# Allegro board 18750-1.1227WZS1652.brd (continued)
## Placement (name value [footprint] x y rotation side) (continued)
PC4521  SCD1U25V2KX-GP  [C402H22]  39.57 35.1 180 top
PC4522  SCD1U25V2KX-GP  [C402H22]  38.92 34.04 0 bottom
PC4523  SC10U25V5KX-GP  [C805H56]  46.48 32.08 180 bottom
PC4524  SC2D2U10V3KX-1GP  [C603H36]  42.57 39.82 0 bottom
PC4525  SC22U6D3V3MX-1-DL-GP  [C603H40]  56.29 130.58 180 top
PC4526  SC1KP50V2KX-1GP  [C402H22]  40.38 39.2 0 bottom
PC4527  SC22U6D3V3MX-1-DL-GP  [C603H40]  54.38 40.13 0 bottom
PC4529  SC22U6D3V3MX-1-DL-GP  [C603H40]  52.05 36.88 180 bottom
PC4530  SCD1U25V2KX-GP  [C402H22]  36.25 38.74 180 bottom
PC4531  SCD1U25V2KX-GP  [C402H22]  37.82 39.93 0 bottom
PC4532  SCD1U25V2KX-GP  [C402H22]  60.6 133.64 270 top
PC4533  SC1KP50V2KX-1GP  [C402H22]  62.89 132.26 90 top
PC4601  SC2200P50V2KX-2DLGP  [C402H22]  70.54 147.83 180 bottom
PC4602  SCD1U16V2KX-3DLGP  [C402H22]  84.89 151.49 90 top
PC4603  SCD1U25V2KX-1-DL-GP  [C402H22]  69.95 150.47 270 bottom
PC4604  SC330P50V2KX-3-DL-GP  [C402H22]  80.67 150.78 90 top
PC4605  SCD047U25V2KX-4-GP  [C402H22]  73.99 148.54 270 bottom
PC4606  SCD22U25V3KX-DL-GP  [C603H36]  74.91 152.4 270 top
PC4607  SC1U10V2KX-1DLGP  [C402H22]  77.6 152.25 0 top
PC4608  SCD022U16V2KX-3DLGP  [C402H22]  73.99 147.78 90 bottom
PC4610  SC33P50V2JN-3DLGP  [C402H22]  81.33 149.84 90 top
PC4611  SC2200P50V2KX-2DLGP  [C402H22]  73.99 150.83 270 bottom
PC4612  SC2200P50V2KX-2DLGP  [C402H22]  86.98 150.87 180 top
PC4613  SCD01U25V2KX-3DLGP  [C402H22]  77.35 151.13 90 top
PC4614  SC470P50V2KX-3DLGP  [C402H22]  86.95 147.98 90 top
PC4615  SCD01U50V2KX-1DLGP  [C402H22]  88.09 148.34 180 top
PC4616  SC1KP50V2KX-1DLGP  [C402H22]  74.08 149.4 270 top
PC4617  SC1KP50V2KX-1DLGP  [C402H22]  72.72 148.06 180 top
PC4618  SC470P50V2KX-3DLGP  [C402H22]  86.59 149.12 0 top
PC4619  SC1KP50V2KX-1DLGP  [C402H22]  88.73 150.32 0 bottom
PC4620  SCD01U50V2KX-1DLGP  [C402H22]  71.94 149.63 180 top
PC4621  SC680P50V2KX-2GP  [C402H22]  73.41 145.14 0 top
PC4622  SCD01U25V2KX-3DLGP  [C402H22]  81.43 148.18 270 top
PC4623  SC2200P50V2KX-2DLGP  [C402H22]  84.22 146.56 0 bottom
PC4624  SC33P50V2JN-3DLGP  [C402H22]  77.35 149.56 90 top
PC4625  SCD022U16V2KX-3DLGP  [C402H22]  87.99 145.96 180 top
PC4626  SCD022U16V2KX-3DLGP  [C402H22]  88.78 145.96 180 top
PC4628  SCD022U16V2KX-3DLGP  [C402H22]  85.8 149.25 270 bottom
PC4629  SC330P50V2KX-3-DL-GP  [C402H22]  77.35 148.77 270 top
PC4630  SCD047U25V2KX-4-GP  [C402H22]  84.52 146.74 90 top
PC4631  SCD1U25V2KX-1-DL-GP  [C402H22]  73.49 145.1 0 bottom
PC4632  SC2200P50V2KX-2DLGP  [C402H22]  75.24 145.72 90 top
PC4633  SCD1U25V2KX-1-DL-GP  [C402H22]  87.2 146.83 180 top
PC4634  SCD047U25V2KX-4-GP  [C402H22]  75.36 145.47 270 bottom
PC4635  SCD01U25V2KX-3DLGP  [C402H22]  69.97 146.99 90 top
PC4637  SCD01U25V2KX-3DLGP  [C402H22]  78.71 146.86 180 top
PC4638  SC330P50V2KX-3-DL-GP  [C402H22]  80.58 146.87 180 top
PC4639  SC33P50V2JN-3DLGP  [C402H22]  79.48 146.86 180 top
PC4640  SC2200P50V2KX-2DLGP  [C402H22]  78.82 144.29 180 top
PC4641  SC330P50V2KX-3-DL-GP  [C402H22]  77.2 144.25 180 top
PC4642  SC1KP50V2KX-1DLGP  [C402H22]  69.88 146.71 270 bottom
PC4643  SC1KP50V2KX-1DLGP  [C402H22]  71.81 144.7 0 bottom
PC4644  SCD01U50V2KX-1DLGP  [C402H22]  78.01 144.25 180 top
PC4651  SC1KP50V2KX-1DLGP  [C402H22]  86.21 150.88 180 top
PC4652  SCD022U16V2KX-3DLGP  [C402H22]  69.96 147.8 90 top
PC4653  SCD047U25V2KX-4-GP  [C402H22]  85.8 148.48 270 bottom
PC4654  SCD022U16V2KX-3DLGP  [C402H22]  85.79 147.71 270 bottom
PC4701  SC10U25V3MX-GP  [C603H40]  69.32 135.61 0 top
PC4702  SC10U25V3MX-GP  [C603H40]  71.78 136.17 90 top
PC4703  SC10U25V3MX-GP  [C603H40]  71.83 138.53 90 top
PC4704  SC10U25V3MX-GP  [C603H40]  71.71 140.03 90 top
PC4706  SC1KP50V2KX-1DLGP  [C402H22]  68.61 132.26 180 top
PC4707  SCD22U25V3KX-DL-GP  [C603H36]  67.67 136.81 180 top
PC4708  SC1U10V2KX-1DLGP  [C402H22]  66.58 139.88 0 bottom
PC4766  SC1U10V2KX-1DLGP  [C402H22]  64.27 135.48 0 top
PC4802  SC10U25V3MX-GP  [C603H40]  86.11 142.17 90 bottom
PC4803  SC10U25V3MX-GP  [C603H40]  86.13 140.69 90 bottom
PC4804  SC10U25V3MX-GP  [C603H40]  86.19 139.24 90 bottom
PC4805  SC10U25V3MX-GP  [C603H40]  87.1 135.61 180 bottom
PC4808  SCD22U25V3KX-DL-GP  [C603H36]  83.54 140.62 180 bottom
PC4809  SC1U10V2KX-1DLGP  [C402H22]  79.35 138.3 180 top
PC4810  SC1KP50V2KX-1DLGP  [C402H22]  85.52 132.26 180 top
PC4811  SCD22U25V3KX-DL-GP  [C603H36]  78.21 136.68 180 top
PC4812  SC1U10V2KX-1DLGP  [C402H22]  75.54 136.32 0 top
PC4813  SC1KP50V2KX-1DLGP  [C402H22]  74.93 132.26 180 top
PC4814  SC10U25V3MX-GP  [C603H40]  78.25 141.38 270 top
PC4815  SC10U25V3MX-GP  [C603H40]  78.25 139.98 90 bottom
PC4816  SC10U25V3MX-GP  [C603H40]  78.25 141.71 90 bottom
PC4817  SC10U25V3MX-GP  [C603H40]  78.46 139.93 270 top
PC4866  SC1U10V2KX-1DLGP  [C402H22]  74.78 136.32 0 top
PC4877  SC1U10V2KX-1DLGP  [C402H22]  80.11 135.61 270 top
PC5001  SC2D2U10V3KX-1DLGP-U  [C603H36]  98.76 139.8 90 bottom
PC5002  SC10U25V5KX-DL-GP  [C805H58]  91.54 138.76 90 bottom
PC5003  SC10U25V5KX-DL-GP  [C805H58]  91.54 140.49 90 bottom
PC5004  SCD1U25V2KX-1-DL-GP  [C402H22]  95.79 138.28 270 bottom
PC5005  SCD22U25V3KX-DL-GP  [C603H36]  97.89 138.43 0 top
PC5102  SCD1U25V2KX-1-DL-GP  [C402H22]  119.74 30.89 270 bottom
PC5103  SC1U10V2KX-L1-GP  [C402H22]  112.04 30.31 180 top
PC5104  SC22U6D3V3MX-L1-GP  [C603H40]  120.88 38.99 270 bottom
PC5105  SC22U6D3V3MX-L1-GP  [C603H40]  111.33 40.23 90 bottom
PC5106  SC22U6D3V3MX-L1-GP  [C603H40]  111.33 39.04 90 bottom
PC5107  SC22U6D3V3MX-L1-GP  [C603H40]  120.88 40.16 270 bottom
PC5111  SC68P50V2JN-1DLGP  [C402H22]  91.39 37.06 90 top
PC5112  SC10U6D3V3MX-DL-GP  [C603H36]  92.5 40.23 0 bottom
PC5113  SC10U6D3V3MX-DL-GP  [C603H36]  93.69 40.22 0 bottom
PC5114  SC1U6D3V1MX-GP  [C0201H14]  117.45 30.13 270 top
PC5115  SC10U25V5KX-L-GP  [C805H56]  120.5 35.71 0 bottom
PC5116  SC10U6D3V3MX-L-GP  [C603H38]  119.18 29.31 180 bottom
PC5117  SC10U6D3V3MX-L-GP  [C603H38]  120.35 29.31 180 bottom
PC5118  SC1500P50V2KX-2GP  [C402H22]  112.25 35.15 0 top
PC5119  SC10U25V5KX-L-GP  [C805H56]  122.23 36.48 0 bottom
PC5120  SC1U10V2KX-1DLGP  [C402H22]  97.64 37.21 270 top
PC5121  SC4D7U6D3V2MX-1-GP  [C402H22]  111.15 30.38 180 top
PC5122  SCD1U25V2KX-1-DL-GP  [C402H22]  115.04 32.89 270 top
PC5123  SCD1U25V2KX-1-DL-GP  [C402H22]  117.5 28.6 270 top
PC5124  SC10U6D3V3MX-DL-GP  [C603H36]  99.89 36.65 270 bottom
PC5127  SCD1U25V2KX-1-DL-GP  [C402H22]  97.67 35.61 270 top
PC5201  SC22U6D3V3MX-1-DL-GP  [C603H40]  105.91 128.92 90 top
PC5202  SC4D7U25V5KX-DL-GP  [C805H54]  98.05 138.33 90 bottom
PC5203  SC22U6D3V3MX-1-DL-GP  [C603H40]  105.91 130.09 90 top
PC5204  SCD1U25V2KX-1-DL-GP  [C402H22]  102.15 135.71 0 top
PC5205  SC22U6D3V3MX-1-DL-GP  [C603H40]  105.91 128.92 270 bottom
PC5206  SC22U6D3V3MX-1-DL-GP  [C603H40]  105.91 130.09 270 bottom
PC5208  SCD1U25V2KX-1-DL-GP  [C402H22]  105.46 127.95 270 bottom
PC5209  SC10U25V5KX-DL-GP  [C805H58]  105.9 138.79 0 bottom
PC5210  SC10U25V5KX-DL-GP  [C805H58]  106.48 134.43 180 bottom
PC5211  SC10U25V5KX-DL-GP  [C805H58]  107.62 138.79 0 bottom
PC5212  SC220P50V2KX-3DLGP  [C402H22]  102.8 141.15 270 bottom
PC5213  SCD01U25V2KX-3DLGP  [C402H22]  100.84 137.19 90 top
PC5214  SCD1U25V2KX-1-DL-GP  [C402H22]  105.24 134.57 180 bottom
PC5215  SC1KP50V2KX-1DLGP  [C402H22]  100.16 141.33 0 bottom
PC5216  SC10U25V5KX-DL-GP  [C805H58]  109.88 140.23 270 bottom
PC5217  SC22U6D3V3MX-1-DL-GP  [C603H40]  98.17 125.05 90 bottom
PC5301  SC22U6D3V3MX-L1-GP  [C603H40]  72.24 36.7 90 bottom
PC5302  SC22U6D3V3MX-L1-GP  [C603H40]  64.82 40.64 90 bottom
PC5303  SC22U6D3V3MX-L1-GP  [C603H40]  67.21 40.64 270 bottom
PC5305  SC22P50V2JN-L-GP  [C402H22]  69.01 40.62 180 bottom
PC5307  SC1U6D3V1MX-GP  [C0201H14]  68.56 40.9 270 top
PC8501  SC10U25V3MX-3-GP  [C603H40]  140.31 81.74 0 top
PC8502  SC10U25V3MX-3-GP  [C603H40]  139.14 81.74 0 top
PC8503  SCD1U25V2KX-1-DL-GP  [C402H22]  141.66 82.73 90 top
PC8504  SC10U25V3MX-3-GP  [C603H40]  157.13 82.17 0 top
PC8505  SC10U25V3MX-3-GP  [C603H40]  154.16 82.83 270 top
PC8506  SCD1U25V2KX-1-DL-GP  [C402H22]  154.97 81.51 0 top
PC8507  SC330P50V2JN-1-DL-GP  [C402H22]  147.41 90.27 0 top
PC8508  SC330P50V2JN-1-DL-GP  [C402H22]  146.57 90.27 0 top
PC8550  SC1U10V2KX-1DLGP  [C402H22]  145.06 81.36 270 top
PC8551  SCD1U25V2KX-1-DL-GP  [C402H22]  143.42 76.4 90 top
PC8552  SC1KP50V2KX-1DLGP  [C402H22]  148.57 78.41 90 bottom
PC8553  SCD1U25V2KX-1-DL-GP  [C402H22]  141.02 78.77 180 bottom
PC8554  SCD01U50V2KX-1DLGP  [C402H22]  140.47 77.04 270 top
PC8555  SC2700P50V2KX-1-DL-GP  [C402H22]  141.46 75.21 225 top
PC8556  SCD1U25V2KX-1-DL-GP  [C402H22]  146.34 78.4 270 top
PC8558  SC47P50V2JN-5DLGP  [C402H22]  139.2 77.98 0 top
PC8559  SC47P50V2JN-5DLGP  [C402H22]  140.06 79.45 180 top
PC8560  SC47P50V2JN-5DLGP  [C402H22]  144.86 78.39 90 top
PC8561  SC10U25V3MX-3-GP  [C603H40]  140.31 81.74 180 bottom
PC8562  SC10U25V3MX-3-GP  [C603H40]  139.14 81.74 180 bottom
PC8572  SCD1U25V2KX-1-DL-GP  [C402H22]  149.91 81.9 0 bottom
PC8573  SC33P50V2JN-3DLGP  [C402H22]  143.93 81.05 180 top
PC8575  SCD1U25V2KX-1-DL-GP  [C402H22]  143.51 82.22 270 bottom
PC8576  SC10U25V3MX-3-GP  [C603H40]  155.93 81.54 0 top
PC8578  SC10U25V3MX-3-GP  [C603H40]  154.18 82.86 90 bottom
PC8602  SC330P50V2KX-3GP  [C402H22]  111 153.7 180 bottom
PC8609  SCD01U25V2KX-3DLGP  [C402H22]  111.75 145.82 180 bottom
PC8610  SC10U25V5KX-GP  [C805H56]  110.47 145.9 180 bottom
PC8611  SC22U6D3V3MX-1-DL-GP  [C603H40]  118.95 150.7 0 bottom
PC8613  SC22U6D3V3MX-1-DL-GP  [C603H40]  120.12 150.7 0 bottom
PC8614  SCD1U16V2KX-3GP  [C402H22]  120.83 144.97 270 bottom
PC8615  SC10U25V5KX-GP  [C805H56]  108.74 145.9 180 bottom
PC8617  SC2D2U10V3KX-1GP  [C603H36]  113.39 151.06 270 bottom
PC8618  SC1U6D3V1MX-GP  [C0201H14]  111.71 152.66 270 bottom
PC8619  SCD1U25V2KX-GP  [C402H22]  113.41 148.85 0 bottom
PC8620  SC22U6D3V3MX-1-DL-GP  [C603H40]  118.95 150.7 180 top
PC8621  SC22U6D3V3MX-1-DL-GP  [C603H40]  117.78 150.7 0 bottom
PC8627  SC10U6D3V3MX-GP  [C603H38]  107.09 143.1 0 bottom
PC8628  SC22U6D3V3MX-1-GP  [C603H40]  117.27 140.51 180 bottom
PC8629  SC1U6D3V1MX-GP  [C0201H14]  109.1 143.26 0 bottom
PC8630  SC10U6D3V3MX-GP  [C603H38]  108.26 143.33 0 bottom
PC8631  SC22U6D3V3MX-1-GP  [C603H40]  116.06 140.51 180 bottom
PC8632  SC22P50V2JN-4GP  [C402H22]  110.82 141.45 270 top
PC8633  SC1U6D3V1MX-GP  [C0201H14]  111.71 152.15 270 bottom
PC8634  SC1U6D3V1MX-GP  [C0201H14]  109.6 143.26 0 bottom
PD4401  BAT54C-12-GP  [SOT-23-9H44]  198.43 42.19 180 bottom
PD4404  L1SS355T1G-GP  [SOD323AKH44]  214.3 45.47 270 bottom
PD4407  RB520S30-GP  [SOD523AKH26]  192.03 39.68 90 bottom
PD4408  BAT54C-12-GP  [SOT-23-9H44]  194.95 40.95 180 bottom
PD4409  RB520S30-GP  [SOD523AKH26]  191.7 41.53 0 bottom
PD5101  AZ4024-01L-R7G-GP  [SOD323AKH40]  117.17 31.45 90 top
PG4401  GAP-CLOSE-PWR-3-GP  [GAP-CLOSE-PWR-3]  183.87 56.31 0 bottom
PG4402  GAP-CLOSE-PWR-3-GP  [GAP-CLOSE-PWR-3]  185.4 56.31 180 bottom
PG4405  GAP-CLOSE-PWR-3-GP  [GAP-CLOSE-PWR-3]  173.49 40.64 90 bottom
PG4406  GAP-CLOSE-PWR-3-GP  [GAP-CLOSE-PWR-3]  171.96 40.64 90 bottom
PG4408  GAP-CLOSE-PWR-3-GP  [GAP-CLOSE-PWR-3]  209.29 41.59 90 top
PG4415  GAP-CLOSE-PWR-0805-NP-5-GP  [GAP-CLOSE-PWR-0805-NP-5]  183.09 38.28 270 bottom
PG4419  GAP-CLOSE-PWR-0805-NP-5-GP  [GAP-CLOSE-PWR-0805-NP-5]  185.04 59.23 90 bottom
PG4422  GAP-CLOSE-PWR-0805-NP-5-GP  [GAP-CLOSE-PWR-0805-NP-5]  172.06 33.48 180 bottom
PG4423  GAP-CLOSE-PWR-0805-NP-5-GP  [GAP-CLOSE-PWR-0805-NP-5]  176.15 39.93 180 bottom
PG4527  GAP-CLOSE-PWR-3-GP  [GAP-CLOSE-PWR-3]  42.45 39.35 90 top
PG4528  GAP-CLOSE-PWR-3-GP  [GAP-CLOSE-PWR-3]  44.28 37.77 0 top
PG4530  GAP-CLOSE-PWR-3-GP  [GAP-CLOSE-PWR-3]  62.07 130.99 270 top
PG4532  GAP-CLOSE-PWR-3-GP  [GAP-CLOSE-PWR-3]  62.34 132.33 90 bottom
PG4707  GAP-CLOSE-PWR-3-GP  [GAP-CLOSE-PWR-3]  67.34 129.11 90 bottom
PG4708  GAP-CLOSE-PWR-3-GP  [GAP-CLOSE-PWR-3]  67.34 126.95 270 bottom
PG4808  GAP-CLOSE-PWR-3-GP  [GAP-CLOSE-PWR-3]  84.46 129.06 90 bottom
PG4809  GAP-CLOSE-PWR-3-GP  [GAP-CLOSE-PWR-3]  84.46 126.9 270 bottom
PG4813  GAP-CLOSE-PWR-3-GP  [GAP-CLOSE-PWR-3]  76.84 129.08 90 bottom
PG4815  GAP-CLOSE-PWR-3-GP  [GAP-CLOSE-PWR-3]  76.84 126.85 270 bottom
PG5001  GAP-CLOSE-PWR-3-GP  [GAP-CLOSE-PWR-3]  92.94 128.78 270 bottom
PG5002  GAP-CLOSE-PWR-3-GP  [GAP-CLOSE-PWR-3]  94.36 139.96 0 bottom
PG5003  GAP-CLOSE-PWR-3-GP  [GAP-CLOSE-PWR-3]  94.36 139.19 0 bottom
PG5011  GAP-CLOSE-PWR-3-GP  [GAP-CLOSE-PWR-3]  92.94 130.94 90 bottom
PG5101  GAP-CLOSE-PWR-3-GP  [GAP-CLOSE-PWR-3]  120.12 34.11 270 top
PG5102  GAP-CLOSE-PWR-3-GP  [GAP-CLOSE-PWR-3]  120.88 34.11 270 top
PG5103  GAP-CLOSE-PWR-3-GP  [GAP-CLOSE-PWR-3]  115.52 42.33 90 top
PG5104  GAP-CLOSE-PWR-3-GP  [GAP-CLOSE-PWR-3]  121.64 34.11 270 top
PG5105  GAP-CLOSE-PWR-3-GP  [GAP-CLOSE-PWR-3]  114.75 42.33 90 top
PG5106  GAP-CLOSE-PWR-3-GP  [GAP-CLOSE-PWR-3]  116.28 42.33 90 top
PG5107  GAP-CLOSE-PWR-3-GP  [GAP-CLOSE-PWR-3]  118.56 42.33 90 top
PG5108  GAP-CLOSE-PWR-3-GP  [GAP-CLOSE-PWR-3]  117.8 42.33 90 top
PG5109  GAP-CLOSE-PWR-3-GP  [GAP-CLOSE-PWR-3]  117.04 42.33 90 top
PG5110  GAP-CLOSE-PWR-3-GP  [GAP-CLOSE-PWR-3]  121.21 42.32 270 top
PG5111  GAP-CLOSE-PWR-3-GP  [GAP-CLOSE-PWR-3]  119.97 41.3 180 top
PG5112  GAP-CLOSE-PWR-3-GP  [GAP-CLOSE-PWR-3]  94.9 39.6 180 top
PG5113  GAP-CLOSE-PWR-3-GP  [GAP-CLOSE-PWR-3]  94.9 40.36 180 top
PG5114  GAP-CLOSE-PWR-3-GP  [GAP-CLOSE-PWR-3]  82.26 36.51 270 top
PG5116  GAP-CLOSE-PWR-3-GP  [GAP-CLOSE-PWR-3]  121.97 42.32 270 top
PG5122  GAP-CLOSE-PWR-3-GP  [GAP-CLOSE-PWR-3]  99.19 35.92 180 top
PG5201  GAP-CLOSE-PWR-3-GP  [GAP-CLOSE-PWR-3]  99.85 126.26 270 top
PG5202  GAP-CLOSE-PWR-3-GP  [GAP-CLOSE-PWR-3]  99.09 126.26 270 top
PG5203  GAP-CLOSE-PWR-3-GP  [GAP-CLOSE-PWR-3]  102.14 126.26 270 top
PG5204  GAP-CLOSE-PWR-3-GP  [GAP-CLOSE-PWR-3]  103.66 126.26 270 top
PG5205  GAP-CLOSE-PWR-3-GP  [GAP-CLOSE-PWR-3]  104.42 126.26 270 top
PG5206  GAP-CLOSE-PWR-3-GP  [GAP-CLOSE-PWR-3]  101.37 126.26 270 top
PG5207  GAP-CLOSE-PWR-3-GP  [GAP-CLOSE-PWR-3]  102.9 126.26 270 top
PG5208  GAP-CLOSE-PWR-3-GP  [GAP-CLOSE-PWR-3]  105.18 126.26 270 top
PG5209  GAP-CLOSE-PWR-3-GP  [GAP-CLOSE-PWR-3]  105.95 126.26 270 top
PG5210  GAP-CLOSE-PWR-3-GP  [GAP-CLOSE-PWR-3]  106.1 137.64 270 top
PG5211  GAP-CLOSE-PWR-3-GP  [GAP-CLOSE-PWR-3]  100.61 126.26 270 top
PG5212  GAP-CLOSE-PWR-3-GP  [GAP-CLOSE-PWR-3]  106.86 137.64 270 top
PG5214  GAP-CLOSE-PWR-3-GP  [GAP-CLOSE-PWR-3]  107.62 137.64 270 top
PG5223  GAP-CLOSE-PWR-6-GP  [GAP-CLOSE-PWR]  105.62 126.24 180 bottom
PG5301  GAP-CLOSE-PWR-3-GP  [GAP-CLOSE-PWR-3]  74.18 37.46 180 bottom
PG5302  GAP-CLOSE-PWR-3-GP  [GAP-CLOSE-PWR-3]  74.18 36.69 180 bottom
PG5303  GAP-CLOSE-PWR-3-GP  [GAP-CLOSE-PWR-3]  60.76 41.91 180 top
PG5304  GAP-CLOSE-PWR-3-GP  [GAP-CLOSE-PWR-3]  60.76 40.39 180 top
PG5305  GAP-CLOSE-PWR-3-GP  [GAP-CLOSE-PWR-3]  60.76 41.15 180 top
PG8605  GAP-CLOSE-PWR-3-GP  [GAP-CLOSE-PWR-3]  106.94 141.15 90 bottom
PG8608  GAP-CLOSE-PWR-3-GP  [GAP-CLOSE-PWR-3]  118.11 143.82 0 top
PG8609  GAP-CLOSE-PWR-3-GP  [GAP-CLOSE-PWR-3]  120.84 148.11 0 top
PG8610  GAP-CLOSE-PWR-3-GP  [GAP-CLOSE-PWR-3]  120.84 147.35 0 top
PG8611  GAP-CLOSE-PWR-3-GP  [GAP-CLOSE-PWR-3]  120.84 146.59 0 top
PG8612  GAP-CLOSE-PWR-3-GP  [GAP-CLOSE-PWR-3]  120.84 145.83 0 top
PG8613  GAP-CLOSE-PWR-3-GP  [GAP-CLOSE-PWR-3]  116.28 150.23 90 top
PG8614  GAP-CLOSE-PWR-3-GP  [GAP-CLOSE-PWR-3]  110.62 146.23 90 top
PG8615  GAP-CLOSE-PWR-3-GP  [GAP-CLOSE-PWR-3]  108.33 146.23 90 top
PG8616  GAP-CLOSE-PWR-3-GP  [GAP-CLOSE-PWR-3]  109.1 146.23 90 top
PG8617  GAP-CLOSE-PWR-3-GP  [GAP-CLOSE-PWR-3]  109.86 146.23 90 top
PG8618  GAP-CLOSE-PWR-3-GP  [GAP-CLOSE-PWR-3]  120.84 146.6 0 bottom
PG8619  GAP-CLOSE-PWR-3-GP  [GAP-CLOSE-PWR-3]  120.84 147.36 0 bottom
PG8620  GAP-CLOSE-PWR-3-GP  [GAP-CLOSE-PWR-3]  120.84 148.12 0 bottom
PG8621  GAP-CLOSE-PWR-3-GP  [GAP-CLOSE-PWR-3]  120.84 145.83 0 bottom
PG8622  GAP-CLOSE-PWR-3-GP  [GAP-CLOSE-PWR-3]  118.11 143.05 0 top
PL4401  COIL-2D2UH-11-GP  [L11510030H158]  184.97 49.79 90 bottom
PL4402  COIL-4D7UH-33-GP  [L7066-1830-UH119]  184.97 49.79 90 bottom
PL4501  IND-1D5UH-23-GP-U  [L7066-1830-UH119]  57.74 126.8 90 bottom
PL4502  IND-1D5UH-23-GP-U  [L7066-1830-UH119]  47.35 37.69 270 bottom
PL4701  IND-D15UH-33-GP  [L7366-1830H119]  67.41 127.99 180 bottom
PL4702  HCB2012KF-800T50-GP-U  [L20125H42]  71.78 142.98 90 bottom
PL4703  HCB2012KF-800T50-GP-U  [L20125H42]  71.78 141.25 90 bottom
PL4801  IND-D15UH-33-GP  [L7366-1830H119]  84.03 127.99 180 bottom
PL4802  IND-D15UH-33-GP  [L7366-1830H119]  76.79 127.99 180 bottom
PL4803  HCB2012KF-800T50-GP-U  [L20125H42]  94.39 143.05 90 bottom
PL4804  HCB2012KF-800T50-GP-U  [L20125H42]  94.39 141.33 90 bottom
PL5001  IND-D47UH-22-GP-U  [L7066-1830-UH119]  92.94 129.8 180 bottom
PL5101  COIL-1UH-34-GP-U1  [L7066-1830-UH119]  116.08 36.73 0 bottom
PL5201  COIL-1UH-34-GP-U1  [L7066-1830-UH119]  101.14 129.77 180 bottom
PL5301  IND-1UH-300-GP  [L2520-D620H48]  66.55 37.92 0 bottom
PL8508  COIL-D15UH-2-GP  [L7366-1930H158]  150.82 93.41 0 bottom
PL8509  COIL-D15UH-2-GP  [L7366-1930H158]  143.66 93.41 0 bottom
PL8602  IND-1UH-300-GP  [L2520-D620H48]  114.81 142.98 270 bottom
PL8603  COIL-1UH-73-GP  [L4947-1115H119]  116.98 146.85 270 bottom
PQ4402  2N7002K-2-GP  [SOT23DGS2D4H44]  159.85 94.49 180 bottom
PQ4405  2N7002KDW-1-GP  [SOT-363H44]  205.12 44.32 270 bottom
PQ4408  MMBT3906-5-GP-U  [SOT23CBE2D4H46-U]  210.7 44.65 180 bottom
PQ4415  2N7002KDW-1-GP  [SOT-363H44]  207.93 42.04 180 bottom
PQ4416  2N7002KDW-1-GP  [SOT-363H44]  207.52 46.2 0 bottom
PQ4417  2N7002K-2-GP  [SOT23DGS2D4H44]  11.23 128.78 180 top
PQ4418  2N7002KDW-1-GP  [SOT-363H44]  11.76 125.76 180 top
PR4401  D02R6F-GP  [R1206H24]  184.64 56.32 270 bottom
PR4402  2D2R3-1-U-GP  [R603H22]  200.66 54.13 180 bottom
PR4403  2D2R5J-1-GP  [R805H24]  207.57 52.68 270 bottom
PR4404  402KR2F-GP  [R402H16]  207.19 52.76 0 top
PR4405  4D7R2F-GP  [R402H16]  198.41 53.17 90 bottom
PR4406  100KR2F-L1-GP  [R402H16]  203.66 51.08 0 top
PR4407  D01R3721F-GP-U  [R3720H40]  172.77 38.46 90 bottom
PR4409  100KR2F-L1-GP  [R402H16]  205.62 44.96 0 top
PR4410  105KR2F-1-GP  [R402H16]  202.88 47.51 90 top
PR4411  499R2F-2-GP  [R402H16]  196.04 45.01 270 top
PR4412  -  [0R0402-PAD]  202.59 44.65 0 bottom
PR4413  7K32R2F-GP  [R402H16]  201.22 47.64 90 top
PR4414  -  [0R0805-PAD]  193.14 52.45 0 top
PR4416  2D2R3J-2-GP  [R603H22]  194.88 50.38 0 top
PR4417  100KR2F-L1-GP  [R402H16]  205.29 48.8 90 top
PR4420  0R3J-0-U-GP  [R603H22]  186.36 44.25 270 top
PR4422  1R2F-GP  [R402H16]  193.16 54.97 90 top
PR4423  1R2F-GP  [R402H16]  193.16 55.76 90 top
PR4424  1R2F-GP  [R402H16]  184.89 42.04 90 top
PR4425  1R2F-GP  [R402H16]  184.89 42.83 90 top
PR4426  196KR2F-GP  [R402H16]  207.5 47.79 90 top
PR4427  100KR2F-L2-GP  [R402H16]  207.64 41.67 0 top
PR4429  100KR2F-L2-GP  [R402H16]  208.43 41.67 0 top
PR4430  -  [0R0402-PAD]  13.67 129.74 180 top
PR4431  100KR2J-1-GP  [R402H16]  16.01 129.24 0 top
PR4432  10KR2F-2-GP  [R402H16]  9.99 113.72 180 bottom
PR4433  -  [0R0402-PAD]  13.41 124.33 0 top
PR4434  0R2F-1-GP  [R402H16]  203.68 52.91 270 top
PR4435  100KR2F-L3-GP  [R402H16]  207.56 48.04 90 bottom
PR4436  1MR2J-1-GP  [R402H16]  210.39 45.71 270 top
PR4437  0R2F-1-GP  [R402H16]  205.82 52.68 90 top
PR4438  0R2J-2-GP  [R402H16]  198.06 48.23 90 top
PR4439  1KR2F-3-GP  [R402H16]  196.87 51.95 0 top
PR4441  0R3J-0-U-GP  [R603H22]  198.27 49.83 180 top
PR4442  0R2F-1-GP  [R402H16]  196.95 46.69 270 top
PR4443  0R3J-0-U-GP  [R603H22]  199.62 44.32 0 bottom
PR4444  0R3J-0-U-GP  [R603H22]  197.34 49.46 90 bottom
PR4445  0R2F-1-GP  [R402H16]  199 50.79 180 bottom
PR4446  0R3J-0-U-GP  [R603H22]  183.04 44.87 90 top
PR4447  127KR2F-GP  [R402H16]  195.46 38.53 90 top
PR4448  200KR2F-L-GP  [R402H16]  195.08 39.93 0 top
PR4449  200KR2F-L-GP  [R402H16]  207.02 49.9 0 top
PR4450  10KR2F-2-GP  [R402H16]  205.9 43.64 90 top
PR4451  95K3R2F-GP  [R402H16]  205.29 48.01 270 top
PR4452  0R2F-1-GP  [R402H16]  212.07 45.72 90 top
PR4453  0R2F-1-GP  [R402H16]  201.22 48.4 270 top
PR4462  -  [0R0402-PAD]  207.7 46.2 270 top
PR4463  0R2J-2-GP  [R402H16]  207.49 46.98 270 top
PR4464  0R2F-1-GP  [R402H16]  192.15 43.36 270 bottom
PR4465  0R2F-1-GP  [R402H16]  193.17 42.34 270 bottom
PR4472  100KR2F-L3-GP  [R402H16]  207.02 45 180 top
PR4473  100KR2J-1-GP  [R402H16]  209.86 43.89 180 top
PR4474  100KR2F-L1-GP  [R402H16]  205.69 40.31 270 top
PR4475  680KR2F-GP  [R402H16]  207.79 45 0 top
PR4476  -  [0R0402-PAD]  205.28 42.46 90 bottom
PR4477  0R2F-1-GP  [R402H16]  212.04 44.93 90 top
PR4478  1KR2F-3-GP  [R402H16]  200.6 44.83 180 bottom
PR4480  0R2F-1-GP  [R402H16]  197.16 47.45 270 top
PR4484  0R2F-1-GP  [R402H16]  205.61 51.39 90 top
PR4485  182KR2F-GP  [R402H16]  205.21 49.99 0 top
PR4486  -  [0R0402-PAD]  192.92 43.23 270 top
PR4487  -  [0R0402-PAD]  192.92 43.99 270 top
PR4488  -  [0R0402-PAD]  199.56 55.63 90 top
PR4489  -  [0R0402-PAD]  199.56 56.42 90 top
PR4490  0R2F-1-GP  [R402H16]  199.67 51.46 270 top
PR4491  7K15R2F-L-GP  [R402H16]  202.9 51.59 180 top
PR4492  NTC-220K-5-GP-U  [NTC-402H24-U]  201.63 49.64 0 top
PR4493  0R2F-1-GP  [R402H16]  196.04 45.77 270 top
PR4494  470KR2J-L1-GP  [R402H15]  176.99 36.98 270 top
PR4495  0R2J-2-GP  [R402H16]  191.27 44.12 90 bottom
PR4497  100KR2F-L1-GP  [R402H16]  13.34 124.39 180 bottom
PR4498  -  [0R0402-PAD]  13.34 127.89 180 top
PR4499  0R2J-L-GP  [R402H15]  13.87 126.21 45 top
PR4501  -  [0R0603-PAD]  59.61 131.48 90 top
PR4502  -  [0R0603-PAD]  41.18 34.96 270 top
PR4504  0R0402-PAD-1-GP  [0R0402-PAD]  35.26 39.9 0 bottom
PR4505  100KR2J-1-GP  [R402H16]  61.88 135.36 90 bottom
PR4506  1KR2F-3-GP  [R402H16]  63.35 130.94 180 top
PR4507  1KR2F-3-GP  [R402H16]  41.48 39.47 0 top
PR4508  200KR2F-L1-GP  [R402H16]  60.54 134.44 270 top
PR4509  1KR2F-3-GP  [R402H16]  62.21 135.21 270 top
PR4511  1KR2F-3-GP  [R402H16]  36.25 37.21 0 bottom
PR4512  200KR2F-L1-GP  [R402H16]  37.6 38.41 90 bottom
PR4513  1MR2J-1-GP  [R402H16]  37.06 39.9 0 bottom
PR4514  1MR2J-1-GP  [R402H16]  60.52 132.83 270 top
PR4516  0R0402-PAD-1-GP  [0R0402-PAD]  64.11 133.4 270 top
PR4551  348KR2F-GP  [R402H16]  39.58 39.14 0 bottom
PR4601  0R0402-PAD-1-GP  [0R0402-PAD]  72.74 149.73 180 top
PR4602  0R0402-PAD-1-GP  [0R0402-PAD]  74.01 150.19 270 top
PR4603  1KR2F-3-GP  [R402H16]  83.71 152.17 180 top
PR4604  100R2F-L3-GP  [R402H16]  79.05 152.17 180 top
PR4605  75R2F-2-GP  [R402H16]  81.38 152.17 180 top
PR4606  45D3R2F-L-GP  [R402H16]  82.93 152.17 180 top
PR4607  100R2F-L3-GP  [R402H16]  80.85 153.65 180 bottom
PR4608  100KR2F-L1-GP  [R402H16]  86.24 150.78 90 bottom
PR4609  10KR2F-L1-GP  [R402H15]  82.88 153.7 180 bottom
PR4610  1R2J-GP  [R402H16]  77.7 153.65 180 bottom
PR4611  NTC-10K-29-GP-U  [NTC-402H22-U]  97.16 130.74 180 bottom
PR4612  0R0402-PAD-1-GP  [0R0402-PAD]  76.91 153.65 180 bottom
PR4613  0R2J-L-GP  [R402H15]  72.82 148.21 180 bottom
PR4614  0R2J-L-GP  [R402H15]  83.8 151.97 0 bottom
PR4615  1KR2F-3-GP  [R402H16]  72.27 150.8 270 bottom
PR4616  13K7R2F-GP  [R402H16]  83.42 150.04 270 bottom
PR4617  NTC-470K-17-GP  [NTC-402H22-U]  81.28 138.99 270 bottom
PR4618  11KR2F-L-GP  [R402H16]  73.99 149.3 90 bottom
PR4620  412R2F-GP  [R402H16]  73.99 150.06 270 bottom
PR4621  27K4R2F-GP  [R402H16]  86.24 150.01 90 bottom
PR4622  10R2F-L1-GP  [R402H16]  78.49 153.65 180 bottom
PR4623  0R0402-PAD-1-GP  [0R0402-PAD]  79.28 153.65 180 bottom
PR4624  49D9R2F-L1-GP  [R402H16]  80.06 153.65 180 bottom
PR4625  2K61R2F-1-GP  [R402H16]  74.09 146.99 90 bottom
PR4626  3K3R2F-2-GP  [R402H16]  83.49 150.5 270 top
PR4627  100R2F-L1-GP-U  [R402H14]  77.31 150.34 270 top
PR4628  9K31R2F-GP  [R402H16]  75.33 153.66 0 bottom
PR4629  100KR2F-L1-GP  [R402H16]  76.11 153.66 0 bottom
PR4630  2KR2F-L1-GP  [R402H16]  85.4 147.98 270 top
PR4631  100R2F-L1-GP-U  [R402H14]  89.11 148.31 180 top
PR4632  301R2F-GP  [R402H16]  74.06 147.6 90 top
PR4633  2K55R2F-GP  [R402H16]  85.4 148.77 270 top
PR4636  499R2F-2-GP  [R402H16]  85.4 149.56 270 top
PR4637  1K78R2F-GP  [R402H16]  74.05 148.39 270 top
PR4638  2KR2F-L1-GP  [R402H16]  72.65 145.16 180 top
PR4639  100R2F-L1-GP-U  [R402H14]  81.33 148.97 270 top
PR4640  2K49R2F-2-L-GP  [R402H16]  71.33 147.96 0 bottom
PR4641  2K61R2F-1-GP  [R402H16]  91.22 146.57 180 top
PR4642  523R2F-GP  [R402H16]  85 146.51 180 bottom
PR4643  11KR2F-L-GP  [R402H16]  84.57 145.94 90 top
PR4644  40K2R2F-GP  [R402H16]  77.3 147.98 90 top
PR4645  1KR2F-L1-GP  [R402H15]  84.62 145.32 270 bottom
PR4646  NTC-10K-29-GP-U  [NTC-402H22-U]  88.97 129.43 180 bottom
PR4647  0R0402-PAD-1-GP  [0R0402-PAD]  89.65 146.59 180 top
PR4648  348R2F-GP  [R402H16]  75.26 146.23 90 bottom
PR4649  0R0402-PAD-1-GP  [0R0402-PAD]  72.65 145.21 180 bottom
PR4650  NTC-10K-29-GP-U  [NTC-402H22-U]  63.45 128.93 0 bottom
PR4651  1KR2F-L1-GP  [R402H15]  74.48 144.3 0 top
PR4652  11KR2F-L-GP  [R402H16]  76.03 144.2 180 bottom
PR4653  2K61R2F-1-GP  [R402H16]  69.88 146.2 270 top
PR4654  NTC-470K-17-GP  [NTC-402H22-U]  62.76 134.1 180 bottom
PR4655  27K4R2F-GP  [R402H16]  80.11 144.65 90 top
PR4656  2K87R2F-1-GP  [R402H16]  79.13 144.22 180 bottom
PR4657  2KR2F-L1-GP  [R402H16]  76.79 144.24 180 bottom
PR4658  499R2F-2-GP  [R402H16]  78.35 144.24 180 bottom
PR4659  100R2F-L1-GP-U  [R402H14]  77.93 146.81 0 top
PR4660  1K91R2F-1-GP  [R402H16]  77.57 144.25 180 bottom
PR4661  84K5R2F-GP  [R402H16]  81.35 146.97 180 top
PR4662  10KR2F-L1-GP  [R402H15]  79.9 144.22 180 bottom
PR4663  100R2F-L1-GP-U  [R402H14]  71.03 145.26 0 bottom
PR4665  0R0402-PAD-1-GP  [0R0402-PAD]  90.02 149.89 90 bottom
PR4666  0R0402-PAD-1-GP  [0R0402-PAD]  90 150.69 90 bottom
PR4667  0R0402-PAD-1-GP  [0R0402-PAD]  70.25 145.43 0 bottom
PR4668  0R0402-PAD-1-GP  [0R0402-PAD]  69.45 145.44 0 bottom
PR4669  0R2J-L-GP  [R402H15]  82.78 146.64 0 bottom
PR4670  1KR2F-3-GP  [R402H16]  90.07 144.81 90 top
PR4671  0R2F-1-GP  [R402H16]  85.02 151.54 270 bottom
PR4701  0R0402-PAD-1-GP  [0R0402-PAD]  74.45 144.25 0 bottom
PR4702  0R0402-PAD-1-GP  [0R0402-PAD]  64.52 139.96 0 bottom
PR4703  2D2R6J-3-GP  [R1206H28]  67.26 130.43 90 top
PR4704  2D2R2F-GP  [R402H16]  67.34 140.21 0 bottom
PR4705  2D2R3F-L-GP  [R603H24]  66.45 136.81 180 top
PR4706  0R0402-PAD-1-GP  [0R0402-PAD]  65.28 139.96 0 bottom
PR4708  3K65R2F-1-GP  [R402H16]  75.24 144.2 0 bottom
PR4802  0R0402-PAD-1-GP  [0R0402-PAD]  80.98 144.27 0 bottom
PR4803  2D2R2F-GP  [R402H16]  79.53 136.78 0 top
PR4804  2D2R3-1-U-GP  [R603H22]  82.35 140.62 180 bottom
PR4805  2D2R6J-3-GP  [R1206H28]  84.03 130.43 90 top
PR4806  0R0402-PAD-1-GP  [0R0402-PAD]  81.77 144.27 0 bottom
PR4808  3K65R2F-1-GP  [R402H16]  87.1 144.07 90 top
PR4809  10R2F-L1-GP  [R402H16]  86.39 143.56 180 bottom
PR4810  2D2R3-1-U-GP  [R603H22]  77.04 136.68 180 top
PR4811  0R0402-PAD-1-GP  [0R0402-PAD]  82.4 145.8 270 top
PR4812  0R0402-PAD-1-GP  [0R0402-PAD]  82.55 144.27 0 bottom
PR4813  2D2R2F-GP  [R402H16]  74.96 137.54 270 top
PR4814  2D2R6J-3-GP  [R1206H28]  76.56 130.43 270 top
PR4815  10R2F-L1-GP  [R402H16]  84.46 144.2 270 bottom
PR4816  3K65R2F-1-GP  [R402H16]  84.43 143.28 90 bottom
PR4821  100KR2F-L1-GP  [R402H16]  86.39 145.16 180 bottom
PR4822  100KR2F-L1-GP  [R402H16]  87.1 143.28 270 top
PR4823  100KR2F-L1-GP  [R402H16]  84.43 143.74 270 top
PR4824  100KR2F-L1-GP  [R402H16]  84.43 144.53 90 top
PR5001  2D2R3F-L-GP  [R603H24]  96.68 138.41 0 top
PR5003  3K65R2F-1-GP  [R402H16]  93.09 149.86 270 top
PR5004  0R0402-PAD-1-GP  [0R0402-PAD]  93.27 151.23 270 top
PR5101  100KR2J-1-GP  [R402H16]  109.76 27.84 90 top
PR5102  6K49R2F-1-GP  [R402H16]  113.29 29.94 90 top
PR5103  6K2R2F-GP  [R402H16]  119.05 28.6 90 top
PR5104  10K2R2F-GP  [R402H16]  120.65 27.74 90 top
PR5105  -  [0R0603-PAD]  119.79 29.87 90 top
PR5106  510KR2F-GP  [R402H16]  114.89 29.95 270 top
PR5108  10R2J-L-GP  [R402H16]  111.31 29.11 90 top
PR5109  47KR2J-2-GP  [R402H16]  97.69 34.85 270 top
PR5110  2D2R5J-1-GP  [R805H24]  114.05 35.23 270 top
PR5112  100KR2F-L1-GP  [R402H16]  100.71 35.99 270 top
PR5114  1MR2J-1-GP  [R402H16]  97.62 36.4 270 top
PR5117  0R0402-PAD-1-GP  [0R0402-PAD]  97.92 33.63 0 top
PR5119  29K4R2F-GP  [R402H16]  91.19 35.38 90 top
PR5120  13K7R2F-GP  [R402H16]  91.19 34.6 270 top
PR5121  0R0402-PAD-1-GP  [0R0402-PAD]  91.39 38.61 270 top
PR5122  0R0402-PAD-1-GP  [0R0402-PAD]  91.39 37.85 270 top
PR5201  88K7R2F-GP  [R402H16]  103.99 139.12 90 bottom
PR5202  3K16R2F-GP  [R402H16]  101.68 140.74 180 bottom
PR5203  100KR2F-L1-GP  [R402H16]  100.92 140.74 0 bottom
PR5204  10KR2F-2-GP  [R402H16]  104.32 140.87 270 bottom
PR5210  -  [0R0402-PAD]  99.37 141.23 0 bottom
PR5304  49K9R2F-L-GP  [R402H16]  70.59 39.98 0 bottom
PR5305  100KR2F-L1-GP  [R402H16]  69.8 40.49 180 bottom
PR5306  100KR2F-L1-GP  [R402H16]  74.04 38.36 90 bottom
PR5308  0R0402-PAD-1-GP  [0R0402-PAD]  69.75 40.46 0 top
PR8501  2D2R5F-2-GP  [R805H24]  149.24 90.97 270 top
PR8502  2D2R5F-2-GP  [R805H24]  144.77 90.95 90 top
PR8503  0R2J-2-GP  [R402H16]  141.23 79.81 270 top
PR8504  100R2F-L1-GP-U  [R402H14]  138.84 79.1 90 top
PR8505  100R2F-L1-GP-U  [R402H14]  138.43 77.67 0 top
PR8508  15K4R2F-GP  [R402H16]  147.2 82.48 90 top
PR8510  -  [0R0402-PAD]  148.97 79.58 90 bottom
PR8512  0R2J-2-GP  [R402H16]  143.51 79.91 270 top
PR8513  0R2J-2-GP  [R402H16]  143.51 79.15 270 top
PR8517  -  [0R0402-PAD]  139.2 79.15 90 bottom
PR8520  -  [0R0402-PAD]  139.2 78.39 90 bottom
PR8522  -  [0R0402-PAD]  151.04 78.4 90 bottom
PR8526  -  [0R0402-PAD]  149.02 80.34 90 bottom
PR8530  100KR2F-L1-GP  [R402H16]  140.54 80.01 270 bottom
PR8551  2D2R3F-L-GP  [R603H24]  146.99 81.36 270 top
PR8552  2D2R2F-GP  [R402H16]  143.4 75.61 90 top
PR8553  499KR2F-1-GP  [R402H16]  144.61 75.72 180 top
PR8556  20KR2F-L-GP  [R402H16]  145.4 75.98 0 top
PR8557  2KR2F-3-GP  [R402H16]  146.18 75.98 0 top
PR8558  20KR2F-L-GP  [R402H16]  146.97 76 180 top
PR8559  18KR2F-GP  [R402H16]  141.58 77.45 0 top
PR8560  0R2J-2-GP  [R402H16]  143.51 77.98 0 top
PR8563  10KR2J-3-GP  [R402H16]  151.04 79.18 90 bottom
PR8564  10KR2J-3-GP  [R402H16]  146.43 79.58 180 top
PR8572  0R3J-0-U-GP  [R603H22]  148.32 81.31 270 bottom
PR8573  160KR2F-GP  [R402H16]  143.16 81.1 180 top
PR8574  0R3J-0-U-GP  [R603H22]  142.19 81.94 0 bottom
PR8576  0R2J-2-GP  [R402H16]  141.23 79.02 90 top
PR8611  100KR2F-L1-GP  [R402H16]  106.33 153.67 180 bottom
PR8613  34K8R2F-1-GP  [R402H16]  112.53 140.64 0 bottom
PR8620  51KR2F-L-GP  [R402H16]  111.76 140.64 180 bottom
PR8626  12KR2F-L-GP  [R402H16]  109.48 153.7 0 bottom
PR8627  15KR2F-GP  [R402H16]  110.24 153.7 180 bottom
PR8630  -  [0R0402-PAD]  106.3 151.82 180 bottom
PR8632  0R2J-L-GP  [R402H15]  108.72 153.67 180 bottom
PR8633  0R3F-1-GP-U  [R603H24]  112.6 147.47 270 bottom
PR8634  -  [0R0402-PAD]  111.31 152.53 270 top
PT4701  SE330U2VDM-4-GP  [CT7343H83]  67.36 121.29 90 bottom
PT4702  ST33U25VDM-5-GP  [CT7343H79]  71.91 136.32 180 bottom
PT4801  SE330U2VDM-4-GP  [CT7343H83]  83.96 121.31 270 bottom
PT4803  SE330U2VDM-4-GP  [CT7343H83]  75.8 121.31 90 bottom
PT4807  ST33U25VDM-5-GP  [CT7343H79]  90.39 145.44 0 bottom
PT4808  ST33U25VDM-5-GP  [CT7343H79]  95.2 147.96 0 bottom
PT8508  SE330U2VDM-4-GP  [CT7343H83]  149.63 105.1 270 bottom
PT8511  SE330U2VDM-4-GP  [CT7343H83]  151.31 100.11 270 bottom
PT8512  SE330U2VDM-4-GP  [CT7343H83]  143.18 100.1 90 bottom
PU4301  AON7403-GP-U  [PPAK-8P-3232H36]  31.37 129.95 270 top
PU4302  AON7403-GP-U  [PPAK-8P-3232H36]  34.77 130.26 0 top
PU4401  ISL9538HRTZ-GP-U  [QFN32J4-G2D85H34]  203.24 49.04 270 bottom
PU4403  AON7380-GP  [PPAK-8P-3232H36]  193.37 54.12 180 bottom
PU4404  AON7380-GP  [PPAK-8P-3232H36]  193.42 50.16 180 bottom
PU4405  AON7380-GP  [PPAK-8P-3232H36]  183.37 41.92 0 bottom
PU4406  AON7380-GP  [PPAK-8P-3232H36]  179.66 41.92 0 bottom
PU4412  AON7403-GP-U  [PPAK-8P-3232H36]  176.1 32.51 0 bottom
PU4413  AON7403-GP-U  [PPAK-8P-3232H36]  179.66 39.23 180 bottom
PU4501  SY8286BRAC-GP  [QFN20Z3-G1D1H36]  59.44 133.09 270 bottom
PU4502  SY8288CRAC-GP  [QFN20Z3-G1D1H36]  41.18 36.07 0 bottom
PU4601  ISL95859CHRTZ-T-1-GP  [QFN40J5-G3D6-DIFF-H34]  79.33 148.95 90 bottom
PU4701  AOZ5038QI-05-GP  [QFN31G5-G4P-9H34]  66.6 135.15 180 bottom
PU4801  AOZ5038QI-05-GP  [QFN31G5-G4P-9H34]  83.59 135.26 180 bottom
PU4802  AOZ5038QI-05-GP  [QFN31G5-G4P-9H34]  77.27 135.21 180 bottom
PU5001  ISL95808HRZ-T-1-GP  [DFN8G2-G1710-U1H40]  97.67 135.66 270 bottom
PU5002  AON7408-GP  [PPAK-8P-3232H36]  93.83 136.53 180 bottom
PU5003  AON7408-GP  [PPAK-8P-3232H36]  89.84 135.28 0 bottom
PU5101  APL5934KAI-TRG-GP-U  [SOIC8-G3530H63]  95.26 36.32 90 bottom
PU5102  G5388K11U-GP  [QFN32J4-G3PH32]  115.7 30.04 0 bottom
PU5201  AOZ2262QI-10-GP-U  [QFN22G4-G2PH42]  102.33 136.35 180 bottom
PU5301  RT5797ALGQW-GP  [DFN8-G125065H32]  69.55 37.92 90 bottom
PU8510  FDMS3600-02-RJK0215-COLAY-GP  [PPAK-8P-G5324H44-COLAY]  153.03 86.2 90 top
PU8512  FDMS3600-02-RJK0215-COLAY-GP  [PPAK-8P-G5324H44-COLAY]  153.03 86.2 270 bottom
PU8514  RT8812AGQW-GP  [QFN20-G1D75H32]  145.22 79.95 90 bottom
PU8515  FDMS3600-02-RJK0215-COLAY-GP  [PPAK-8P-G5324H44-COLAY]  142.39 86.27 270 top
PU8516  FDMS3600-02-RJK0215-COLAY-GP  [PPAK-8P-G5324H44-COLAY]  142.39 86.27 90 bottom
PU8602  SY8288RAC-GP  [QFN20Z3-G1H36]  110.26 149.99 0 bottom
PU8603  RT5797ALGQW-GP  [DFN8-G125065H32]  111.26 142.75 270 bottom
PWR1  PTWO-CON6-21-GP  [196415-06031-3]  212.7 59.8 0 bottom
Q401  2N7002KDW-1-GP  [SOT-363H44]  128.36 100.99 270 bottom
Q501  PJA138KA-GP  [SOT23DGS2D4H44]  103.66 39.68 90 bottom
Q502  2N7002K-2-GP  [SOT23DGS2D4H44]  106.12 39.68 90 bottom
Q1701  PJT138KA-GP  [SOT-363H44]  157.74 70.88 180 top
Q1702  2N7002KDW-1-GP  [SOT-363H44]  155.46 73.8 0 top
Q1801  2N7002KDW-1-GP  [SOT-363H44]  125.78 96.53 90 bottom
Q2408  2N7002K-2-GP  [SOT23DGS2D4H44]  44.68 66.07 270 top
Q2414  2N7002K-2-GP  [SOT23DGS2D4H44]  45.24 70.13 180 top
Q2416  2N7002KDW-1-GP  [SOT-363H44]  23.57 74.8 180 bottom
Q2417  2N7002KDW-1-GP  [SOT-363H44]  34.4 112.44 0 top
Q2505  2N7002K-2-GP  [SOT23DGS2D4H44]  156.19 95.3 90 top
Q2507  PJA3415-GP  [SOT23DGS2D4H44]  162.97 91.14 270 top
Q2510  2N7002K-2-GP  [SOT23DGS2D4H44]  156.19 91.86 90 top
Q2601  2N7002KDW-1-GP  [SOT-363H44]  131.14 110.07 225 bottom
Q2602  2N7002K-2-GP  [SOT23DGS2D4H44]  127.22 111.25 135 bottom
Q2603  MMBT3904-5-GP-U  [SOT23CBE2D4H46-U]  166.88 81.46 180 bottom
Q3201  2N7002K-2-GP  [SOT23DGS2D4H44]  19.21 60.39 180 top
Q4301  PJA138KA-GP  [SOT23DGS2D4H44]  24.38 97.73 270 top
Q4302  MMBT3904-5-GP-U  [SOT23CBE2D4H46-U]  21.01 97.61 0 top
Q4304  LMUN5212T1G-GP  [SOT323CBE2D2H40]  28.41 124.42 0 top
Q4305  LTA024EUB-FS8-GP  [SC70-2D2-312H44]  27.09 126.56 270 top
Q4448  SM2421PSANC-TRG-GP  [SOT23DGS2D4H48]  31.4 125.73 180 top
Q4449  2N7002KDW-1-GP  [SOT-363H44]  28.72 120.39 270 top
Q5501  MMBT3906LT1-1GPU  [SOT23CBE2D4H44]  224.18 66.78 180 top
Q5502  MMBT3906LT1-1GPU  [SOT23CBE2D4H44]  137.21 90.37 0 bottom
Q5504  MMBT3904LT1-2-GP  [SOT-23-9H44]  52.4 61.52 270 top
Q5505  MMBT3904LT1-2-GP  [SOT-23-9H44]  48.31 62.84 90 top
Q5701  2N7002K-2-GP  [SOT23DGS2D4H44]  21.8 94.29 0 top
Q5702  2N7002KDW-1-GP  [SOT-363H44]  21.97 89.59 180 top
Q5703  LMBT3904LT1G-GP  [SOT23CBE2D4H44]  16.37 105.41 90 bottom
Q5801  2N7002KDW-1-GP  [SOT-363H44]  34.01 101.68 90 top
Q6102  2N7002K-2-GP  [SOT23DGS2D4H44]  50.97 108.59 270 top
Q6401  PJA138KA-GP  [SOT23DGS2D4H44]  20.81 34.9 180 bottom
Q6402  2N7002K-2-GP  [SOT23DGS2D4H44]  49.36 58.27 270 top
Q6403  RN2418-GP  [SOT23CBE2D6H62]  10.8 110.31 270 bottom
Q6404  RN2418-GP  [SOT23CBE2D6H62]  14.13 110.11 270 bottom
Q6405  RN2418-GP  [SOT23CBE2D6H62]  197.07 55.53 180 bottom
Q6406  2N7002KDW-1-GP  [SOT-363H44]  26.19 78.13 270 bottom
Q6407  DDTA144EUA-7-F-GP  [SOT-323H44]  43.31 79.05 0 top
Q6408  LMBT3904LT1G-GP  [SOT23CBE2D4H44]  48.82 68.1 180 top
Q6501  PJA138KA-GP  [SOT23DGS2D4H44]  108.59 39.68 90 bottom
Q6502  PJA3415-GP  [SOT23DGS2D4H44]  94.36 28.88 180 bottom
Q6503  2N7002K-2-GP  [SOT23DGS2D4H44]  97.79 28.88 180 bottom
Q6504  2N7002KDW-1-GP  [SOT-363H44]  98.58 32.16 0 bottom
Q6505  RN2418-GP  [SOT23CBE2D6H62]  100.38 39.52 0 bottom
Q7001  2N7002KDW-1-GP  [SOT-363H44]  137.01 94.53 180 top
Q7201  2N7002K-2-GP  [SOT23DGS2D4H44]  57.92 133.03 180 top
Q7401  SM2421PSANC-TRG-GP  [SOT23DGS2D4H48]  31.4 123.24 180 top
Q7404  2N7002KDW-1-GP  [SOT-363H44]  26.27 109.88 180 bottom
Q7405  2N7002KDW-1-GP  [SOT-363H44]  26.39 106 0 bottom
Q7406  2N7002KDW-1-GP  [SOT-363H44]  29.82 108.97 180 top
Q7407  PJT138KA-GP  [SOT-363H44]  28.46 115.24 90 top
Q7408  2N7002K-2-GP  [SOT23DGS2D4H44]  33.59 108.11 180 top
Q7601  PJA138KA-GP  [SOT23DGS2D4H44]  132.24 98.45 270 bottom
Q7901  PJT138KA-GP  [SOT-363H44]  148.54 109.37 90 bottom
Q7906  PJA138KA-GP  [SOT23DGS2D4H44]  130.84 106 270 bottom
Q7907  PJT138KA-GP  [SOT-363H44]  130.77 102.83 180 bottom
Q8101  2N7002K-2-GP  [SOT23DGS2D4H44]  161.04 113.34 90 bottom
Q8701  PJT138KA-GP  [SOT-363H44]  103.43 144.69 180 top
Q8702  PJT138KA-GP  [SOT-363H44]  107.71 151.59 90 top
Q8703  PJT138KA-GP  [SOT-363H44]  106.16 147.02 270 bottom
Q8704  PJT138KA-GP  [SOT-363H44]  102.46 145.14 90 bottom
Q8705  2N7002KDW-1-GP  [SOT-363H44]  105.21 142.7 0 bottom
Q9201  PJA3415-GP  [SOT23DGS2D4H44]  164.6 70.94 0 top
Q9202  2N7002K-2-GP  [SOT23DGS2D4H44]  162.31 72.8 180 top
R301  1KR2J-1-GP  [R402H16]  77.35 113.46 180 bottom
R302  499R2F-2-GP  [R402H16]  76.58 113.46 0 bottom
R304  49D9R2F-GP  [R402H16]  102.62 89.54 0 top
R305  49D9R2F-GP  [R402H16]  105.97 90.81 90 top
R308  1KR2J-1-GP  [R402H16]  92.33 115.01 180 bottom
R309  51R2J-2-GP  [R402H16]  77.04 104.95 180 top
R310  51R2J-2-GP  [R402H16]  79.89 104.95 180 top
R311  51R2J-2-GP  [R402H16]  77.8 104.95 180 top
R312  51R2J-2-GP  [R402H16]  73.28 113.34 0 bottom
R313  51R2J-2-GP  [R402H16]  78.11 113.46 0 bottom
R314  51R2J-2-GP  [R402H16]  72.52 113.34 0 bottom
R315  1KR2J-1-GP  [R402H16]  76.28 104.95 180 top
R316  51R2J-2-GP  [R402H16]  81.03 111.18 0 bottom
R317  51R2J-2-GP  [R402H16]  65.66 100.94 90 bottom
R318  51R2J-2-GP  [R402H16]  65.66 100.18 90 bottom
R319  -  [0R0402-PAD]  106.73 78.84 0 bottom
R401  24D9R2F-L-GP  [R402H16]  84.61 92.46 270 top
R403  100KR2J-1-GP  [R402H16]  125.83 99.39 90 bottom
R404  0R2J-L-GP  [R402H15]  125.45 101.02 180 bottom
R405  10KR2J-3-GP  [R402H16]  126.5 101.91 180 bottom
R406  10KR2J-3-GP  [R402H16]  128.15 99.32 270 bottom
R407  10KR2J-3-GP  [R402H16]  122.86 100.81 270 bottom
R501  121R2F-GP  [R402H16]  99.63 91.15 180 top
R502  80D6R2F-L-GP  [R402H16]  100.41 91.14 180 top
R503  100R2F-L1-GP-U  [R402H14]  101.6 90.72 90 top
R504  0R0402-PAD-1-GP  [0R0402-PAD]  134.8 43.26 180 top
R505  470R2F-GP  [R402H16]  133.99 43.26 0 top
R506  220KR2F-GP  [R402H16]  103.38 37.52 270 bottom
R507  220KR2F-GP  [R402H16]  108.87 29.54 180 top
R601  49D9R2F-GP  [R402H16]  88.84 110.38 0 bottom
R701  -  [0R0402-PAD]  77.85 111.18 0 bottom
R702  -  [0R0402-PAD]  80.01 111.18 0 bottom
R703  220R2J-L2-GP  [R402H16]  78.87 113.46 180 bottom
R704  56R2J-4-GP  [R402H16]  80.61 152.17 180 top
R705  54D9R2F-L1-GP  [R402H16]  82.16 152.17 180 top
R706  100R2F-L1-GP-U  [R402H14]  79.82 152.17 180 top
R707  100R2F-L1-GP-U  [R402H14]  87.65 104.33 90 top
R708  100R2F-L1-GP-U  [R402H14]  87.61 105.2 270 top
R807  100R2F-L1-GP-U  [R402H14]  70.11 109.68 90 bottom
R808  100R2F-L1-GP-U  [R402H14]  68.52 109.68 90 bottom
R809  100R2F-L1-GP-U  [R402H14]  95.03 104.28 180 top
R810  100R2F-L1-GP-U  [R402H14]  95.47 101.55 180 top
R811  GAP-CLOSE-PWR-0805-NP-GP-U  [GAP-CLOSE-PWR-0805-NP]  86.34 101.53 270 top
R812  GAP-CLOSE-PWR-0805-NP-GP-U  [GAP-CLOSE-PWR-0805-NP]  78.78 101.53 270 top
R815  GAP-CLOSE-PWR-0805-NP-GP-U  [GAP-CLOSE-PWR-0805-NP]  83.57 98.45 180 top
R816  GAP-CLOSE-PWR-0805-NP-GP-U  [GAP-CLOSE-PWR-0805-NP]  85.6 98.45 180 top
R817  GAP-CLOSE-PWR-0805-NP-GP-U  [GAP-CLOSE-PWR-0805-NP]  80.72 98.99 270 top
R1103  0R0603-PAD-2-GP-U  [0R0603-PAD-1-U]  126.25 88.78 0 bottom
R1104  0R0603-PAD-2-GP-U  [0R0603-PAD-1-U]  160.73 70.69 0 top
R1204  10KR2F-L1-GP  [R402H15]  95.74 45.82 270 top
R1205  0R0402-PAD-1-GP  [0R0402-PAD]  95.33 44.6 180 top
R1206  2R2F-GP  [R402H16]  73.56 40.87 90 top
R1208  10KR2F-L1-GP  [R402H15]  96.9 46.66 180 top
R1209  24D9R2F-L-GP  [R402H16]  72.67 39.27 270 top
R1210  0R0402-PAD-1-GP  [0R0402-PAD]  97.39 44.98 90 top
R1211  10KR2F-L1-GP  [R402H15]  75.19 40.84 90 top
R1212  0R0402-PAD-1-GP  [0R0402-PAD]  75.19 41.63 90 top
R1215  240R2F-1-GP  [R402H16]  64.72 44.65 180 top
R1216  SC2D2U6D3V2MX-DL-GP  [C402H22]  95.51 49.94 270 top
R1302  10KR2F-L1-GP  [R402H15]  172.65 45.14 270 top
R1303  0R0402-PAD-1-GP  [0R0402-PAD]  173.08 46.36 180 top
R1305  2R2F-GP  [R402H16]  147.22 43.56 270 top
R1306  10KR2F-2-GP  [R402H16]  171.94 44.35 270 top
R1307  0R2J-L-GP  [R402H15]  173.13 43.94 0 top
R1309  24D9R2F-L-GP  [R402H16]  143.94 43.51 270 top
R1310  10KR2F-L1-GP  [R402H15]  151.39 43.59 90 top
R1311  0R0402-PAD-1-GP  [0R0402-PAD]  150.14 43.16 0 top
R1312  240R2F-1-GP  [R402H16]  140.95 44.96 180 top
R1502  1KR2J-1-GP  [R402H16]  138.72 70.08 0 top
R1504  4K7R2J-L-GP  [R402H15]  119.13 98.21 90 bottom
R1506  100KR2F-L2-GP  [R402H16]  164.29 75.74 90 top
R1508  100KR2F-L2-GP  [R402H16]  134.8 90.25 0 bottom
R1510  100KR2F-L2-GP  [R402H16]  127.08 82.53 90 bottom
R1512  4K7R2J-2-GP  [R402H16]  101.91 78.82 0 bottom
R1513  4K7R2J-L-GP  [R402H15]  126.32 87.2 90 bottom
R1515  20KR2J-L2-GP  [R402H16]  37.64 102.47 270 top
R1516  4K7R2J-2-GP  [R402H16]  37.78 103.67 180 top
R1517  1KR2J-1-GP  [R402H16]  73.28 111.63 0 bottom
R1518  1KR2J-1-GP  [R402H16]  68.33 111.43 90 bottom
R1520  4K7R2J-L-GP  [R402H15]  143.65 71.38 0 top
R1521  4K7R2J-L-GP  [R402H15]  144.04 70.19 90 top
R1522  4K7R2J-L-GP  [R402H15]  126.32 86.44 90 bottom
R1524  100KR2F-L2-GP  [R402H16]  139.69 70.56 0 top
R1551  4K7R2J-2-GP  [R402H16]  119.13 97.42 90 bottom
R1554  20K5R2F-GP  [R402H16]  124.68 92.78 270 bottom
R1603  113R2F-GP  [R402H16]  106.98 104.79 270 top
R1604  100R2F-L1-GP-U  [R402H14]  108.72 104.8 270 top
R1606  10KR2J-3-GP  [R402H16]  55.43 28.83 0 top
R1617  10KR2J-3-GP  [R402H16]  195.84 36.76 270 top
R1618  -  [0R0402-PAD]  119.66 100.9 270 bottom
R1619  0R2J-L-GP  [R402H15]  119.66 101.69 270 bottom
R1701  10KR2J-3-GP  [R402H16]  119.66 100.13 90 bottom
R1702  1KR2J-1-GP  [R402H16]  155.44 71.54 0 top
R1707  10KR2J-3-GP  [R402H16]  142.85 70.59 0 top
R1708  0R2J-2-GP  [R402H16]  134.5 69.65 270 top
R1713  -  [0R0402-PAD]  158.37 78.89 180 bottom
R1714  10KR2J-3-GP  [R402H16]  87.96 115.06 0 bottom
R1715  100KR2J-1-GP  [R402H16]  159.13 81.46 270 bottom
R1716  100KR2F-L1-GP  [R402H16]  94.58 114.93 0 bottom
R1717  10KR2J-3-GP  [R402H16]  22.77 59.57 270 bottom
R1718  0R2J-L-GP  [R402H15]  61.78 74.68 90 top
R1719  47KR2F-GP  [R402H16]  95.79 115.3 270 bottom
R1721  10KR2J-3-GP  [R402H16]  145.23 70.66 0 top
R1726  10KR2J-3-GP  [R402H16]  159.07 68.96 90 top
R1730  330KR2J-L1-GP  [R402H16]  169.39 68.16 0 top
R1731  100KR2F-L1-GP  [R402H16]  121.24 100.13 270 bottom
R1737  100KR2J-1-GP  [R402H16]  156.33 75.73 270 top
R1738  10KR2J-3-GP  [R402H16]  137.11 70.09 0 top
R1739  100KR2F-L1-GP  [R402H16]  166.91 79.58 0 top
R1803  60D4R2F-GP  [R402H16]  116.61 114.53 270 bottom
R1804  -  [0R0402-PAD]  121.54 114.94 180 bottom
R1805  33R2F-3-GP  [R402H16]  103.79 75.95 0 top
R1806  0R2J-L-GP  [R402H15]  39.55 95.43 90 top
R1815  10MR2J-L-GP  [R402H16]  119.97 75.85 180 top
R1817  10KR2J-3-GP  [R402H16]  122.3 115.75 0 bottom
R1820  10KR2J-3-GP  [R402H16]  152.87 73.32 0 top
R1821  10KR2J-3-GP  [R402H16]  130.33 71.86 180 top
R1822  10KR2J-3-GP  [R402H16]  34.06 42.44 180 top
R1823  10KR2J-3-GP  [R402H16]  152.08 73.33 0 top
R1824  10KR2J-3-GP  [R402H16]  129.36 98.91 0 bottom
R1825  10KR2J-3-GP  [R402H16]  151.29 73.36 0 top
R1826  10KR2J-3-GP  [R402H16]  47.02 79.55 90 bottom
R1827  10KR2J-3-GP  [R402H16]  41.32 96.5 0 top
R1837  150KR2J-GP  [R402H16]  137.89 70.08 0 top
R1839  33R2J-2-GP  [R402H16]  120.17 114.56 90 bottom
R1840  33R2J-2-GP  [R402H16]  118.6 114.56 90 bottom
R1841  1MR2J-1-GP  [R402H16]  118.65 115.34 90 bottom
R1842  10R2F-L-GP  [R402H14]  135.73 91.25 270 top
R1843  10R2F-L-GP  [R402H14]  134.03 78.5 90 top
R1844  10R2F-L-GP  [R402H14]  135.72 92.03 270 top
R1845  10R2F-L-GP  [R402H14]  136.42 78.44 90 top
R1846  10R2F-L-GP  [R402H14]  133.73 90.22 180 top
R1901  200R2F-L-GP  [R402H16]  111.84 87.05 270 top
R1908  33R2F-3-GP  [R402H16]  104.29 78.82 0 bottom
R1909  1KR2J-1-GP  [R402H16]  102.31 79.99 90 bottom
R1910  10KR2J-3-GP  [R402H16]  149.97 73.77 90 top
R1911  10KR2J-3-GP  [R402H16]  150.09 72.91 270 top
R1912  33R2F-3-GP  [R402H16]  36.12 107.66 90 top
R1913  33R2F-3-GP  [R402H16]  36.12 106.85 90 top
R1920  33R2F-3-GP  [R402H16]  103.53 78.82 0 bottom
R1921  33R2F-3-GP  [R402H16]  102.67 78.82 0 bottom
R2007  10KR2J-3-GP  [R402H16]  128.73 94.77 270 bottom
R2008  10KR2J-3-GP  [R402H16]  127.08 94.77 90 bottom
R2009  10KR2J-3-GP  [R402H16]  122.86 99.29 270 bottom
R2010  10KR2J-3-GP  [R402H16]  122.86 100.05 90 bottom
R2041  10KR2J-3-GP  [R402H16]  119.13 98.99 90 bottom
R2043  10KR2J-3-GP  [R402H16]  212.56 64.36 270 top
R2044  10KR2J-3-GP  [R402H16]  137.44 92.7 270 top
R2045  10KR2J-3-GP  [R402H16]  57 35.66 90 top
R2046  10KR2J-3-GP  [R402H16]  215.6 49.05 0 top
R2047  10KR2J-3-GP  [R402H16]  155.02 39.55 270 top
R2048  51KR2J-1-GP  [R402H16]  117.1 98.58 180 top
R2049  51KR2J-1-GP  [R402H16]  114.81 98.73 180 top
R2051  0R2J-2-GP  [R402H16]  126.7 91.54 270 bottom
R2053  10KR2J-3-GP  [R402H16]  159.36 78.87 0 top
R2054  10KR2J-3-GP  [R402H16]  138.85 95.48 0 bottom
R2055  10KR2J-3-GP  [R402H16]  128.79 105.48 180 top
R2057  33R2F-3-GP  [R402H16]  108.44 75.52 180 top
R2058  33R2F-3-GP  [R402H16]  109.2 75.52 180 top
R2059  10KR2J-3-GP  [R402H16]  204.35 61.27 225 top
R2060  10KR2J-3-GP  [R402H16]  215.47 42.04 180 bottom
R2061  10KR2J-3-GP  [R402H16]  211.92 58.52 0 top
R2062  10KR2J-3-GP  [R402H16]  215.14 50.93 270 bottom
R2063  10KR2J-3-GP  [R402H16]  129.37 90.6 90 bottom
R2064  10KR2J-3-GP  [R402H16]  130.1 91.44 90 bottom
R2065  10KR2J-3-GP  [R402H16]  116.34 98.58 180 top
R2066  10KR2J-3-GP  [R402H16]  115.57 98.58 180 top
R2067  0R2J-2-GP  [R402H16]  126.7 92.3 270 bottom
R2068  10KR2J-3-GP  [R402H16]  212.98 51.33 270 top
R2101  150R2F-1-GP  [R402H16]  112.3 87.91 270 top
R2108  200R2F-L-GP  [R402H16]  119.33 93.71 270 bottom
R2111  10KR2J-3-GP  [R402H16]  112.98 96.22 0 top
R2112  10KR2J-3-GP  [R402H16]  113.08 95.02 90 top
R2113  10KR2J-3-GP  [R402H16]  110.46 90.71 180 top
R2114  10KR2J-3-GP  [R402H16]  109.01 91.08 270 top
R2115  10KR2J-3-GP  [R402H16]  113.59 92.76 180 top
R2116  10KR2J-3-GP  [R402H16]  112.82 92.76 0 top
R2117  10KR2J-3-GP  [R402H16]  112.19 96.22 0 top
R2118  10KR2J-3-GP  [R402H16]  111.36 95.96 0 top
R2119  10KR2J-3-GP  [R402H16]  132.16 76.76 45 top
R2202  0R0603-PAD-2-GP-U  [0R0603-PAD-1-U]  112.98 101.96 180 top
R2203  0R0603-PAD-2-GP-U  [0R0603-PAD-1-U]  105.31 99.91 270 top
R2204  -  [0R0603-PAD]  166.78 67.99 0 top
R2205  -  [0R0603-PAD]  104.88 117.81 270 top
R2402  0R0402-PAD-1-GP  [0R0402-PAD]  41.25 73.56 270 top
R2403  0R2J-L-GP  [R402H15]  20.91 57.1 270 top
R2409  0R2J-L-GP  [R402H15]  18.93 58.17 270 top
R2414  10KR2F-2-GP  [R402H16]  43.59 68.45 90 top
R2415  10KR2J-3-GP  [R402H16]  21.59 61.29 0 bottom
R2417  100KR2J-1-GP  [R402H16]  40.8 67.62 180 top
R2421  330R2J-3-GP  [R402H16]  36.1 77.12 90 top
R2424  20KR2F-L-GP  [R402H16]  23.65 61.7 90 bottom
R2426  10KR2J-3-GP  [R402H16]  23.55 58.75 90 bottom
R2427  0R2J-L-GP  [R402H15]  21.44 38.89 180 bottom
R2428  0R2J-L-GP  [R402H15]  18.62 60.55 180 bottom
R2430  10KR2J-3-GP  [R402H16]  27.18 57.33 270 top
R2432  1KR2J-1-GP  [R402H16]  20.75 75.06 180 top
R2434  100KR2J-1-GP  [R402H16]  17.28 64.29 270 bottom
R2435  -  [0R0402-PAD]  40.9 55.42 0 top
R2436  100KR2J-1-GP  [R402H16]  27.05 40.36 180 bottom
R2437  43R2J-GP  [R402H16]  41.51 71.27 90 top
R2438  0R2J-L-GP  [R402H15]  207.52 59.03 180 top
R2441  100KR2F-L1-GP  [R402H16]  38.36 77.17 180 top
R2442  154KR2F-GP  [R402H16]  39.96 77.17 0 top
R2443  10KR2J-3-GP  [R402H16]  34.88 76.73 0 top
R2444  100KR2F-L1-GP  [R402H16]  34.09 76.66 180 top
R2446  0R0603-PAD-2-GP-U  [0R0603-PAD-1-U]  19.56 69.01 180 top
R2447  0R0402-PAD-1-GP  [0R0402-PAD]  199.09 64.01 90 top
R2448  10KR2F-2-GP  [R402H16]  23.52 62.5 90 bottom
R2449  100KR2J-1-GP  [R402H16]  73.49 34.47 270 top
R2450  100KR2J-1-GP  [R402H16]  72.77 29.34 0 top
R2451  100KR2J-1-GP  [R402H16]  22.13 75.01 90 top
R2452  0R2J-L-GP  [R402H15]  23.19 77.62 0 bottom
R2453  0R2J-L-GP  [R402H15]  25.4 74.42 180 bottom
R2454  100KR2J-1-GP  [R402H16]  27.77 75.05 0 bottom
R2455  0R0402-PAD-1-GP  [0R0402-PAD]  214.51 53.93 180 top
R2459  0R0402-PAD-1-GP  [0R0402-PAD]  199.09 64.77 90 top
R2460  0R0402-PAD-1-GP  [0R0402-PAD]  215.27 53.93 180 top
R2461  0R2J-L-GP  [R402H15]  22.99 77.85 180 top
R2462  0R0402-PAD-1-GP  [0R0402-PAD]  33.3 55.93 0 top
R2463  1KR2J-1-GP  [R402H16]  27.77 73.46 0 bottom
R2465  100KR2J-1-GP  [R402H16]  19.74 62.36 270 top
R2466  0R0402-PAD-1-GP  [0R0402-PAD]  19.74 71.71 90 top
R2467  100KR2J-1-GP  [R402H16]  43.09 53.67 180 top
R2470  0R0402-PAD-1-GP  [0R0402-PAD]  19.54 64.52 90 top
R2471  0R2J-L-GP  [R402H15]  22.36 58.37 180 bottom
R2472  0R0402-PAD-1-GP  [0R0402-PAD]  161.78 92.36 90 bottom
R2476  0R2J-L-GP  [R402H15]  162.99 92.79 0 bottom
R2480  100KR2J-1-GP  [R402H16]  40.87 66.02 180 top
R2483  330R2J-3-GP  [R402H16]  31.5 76.63 0 top
R2489  100KR2J-1-GP  [R402H16]  41.51 70.51 90 top
R2490  -  [0R0402-PAD]  24.74 58.32 180 bottom
R2491  10KR2J-3-GP  [R402H16]  37.65 55.91 270 top
R2492  100KR2J-1-GP  [R402H16]  23.42 67.77 270 bottom
R2495  1KR2J-1-GP  [R402H16]  22.76 71.91 90 bottom
R2496  100KR2J-1-GP  [R402H16]  25.48 71.81 180 bottom
R2497  100KR2J-1-GP  [R402H16]  20.04 60.55 180 bottom
R2498  100KR2J-1-GP  [R402H16]  108.23 31.12 180 top
R2499  100KR2J-1-GP  [R402H16]  94.01 32.23 180 bottom
R2501  33R2F-3-GP  [R402H16]  134.04 79.29 90 top
R2502  33R2F-3-GP  [R402H16]  130.53 90.25 180 bottom
R2503  33R2F-3-GP  [R402H16]  130.81 80.11 270 bottom
R2504  10MR2J-L-GP  [R402H16]  158.2 94.75 180 top
